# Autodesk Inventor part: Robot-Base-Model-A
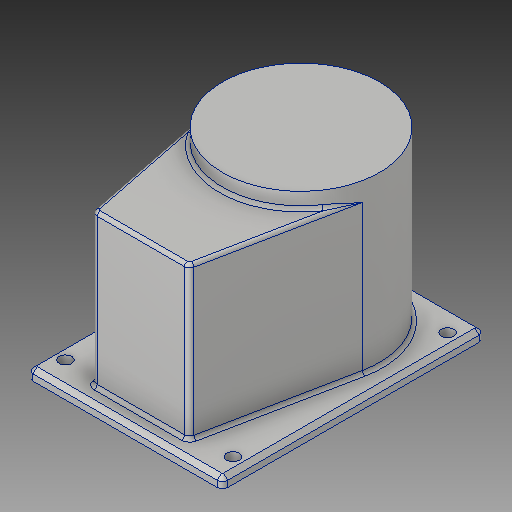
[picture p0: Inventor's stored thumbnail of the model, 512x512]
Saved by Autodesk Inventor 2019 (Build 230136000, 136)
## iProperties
Created: 2018-07
Part Number: Robot-Base-Model-A
Material: Aluminum 6061
Description: 123456
Document SubType Name: Modeling
Designer: Power User
Mass: 12717.4 g
Surface Area: 1979.97 cm^2
Volume: 4710.14 cm^3
Density: 2.7 g/cm^3
Appearance: Aluminum - Flat
Title: GEAR
Author: Power User
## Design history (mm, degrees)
sketch "Sketch6"
  geometry: L1 (93, 125)-(-93, 125); L2 (-93, 125)-(-93, -125); L3 (-93, -125)-(93, -125); L4 (93, -125)-(93, 125); L5 (93, 125)-(-93, -125); L6 (-93, 125)-(93, -125); 1 further point
  constraints: 12 end point, 2 midpoint, 2 parallel, 1 horizontal, 1 perpendicular
  dimensions: "d44" = 250 distance of L3.end L1.start; "d45" = 186 distance of L2.end L3.end
extrude "Extrusion5" new body sketch "Sketch6" distance "d46" = 10; taper "d47" = 0 deg
fillet "Fillet6" dims "d78" = 5
chamfer "Chamfer3" distance "d79" = 4; stored, may be unused: second distance "d80" = 2, angle "d81" = 135 deg
sketch "Sketch7"
  geometry: L1 (-93, -125)-(93, -125) reference; L2 (-73.533, 28.237)-(-45.78, -110); L3 (-45.78, -110)-(45.78, -110); L4 (45.78, -110)-(73.533, 28.237); A1 r 75 centre (0, 43) between (-73.533, 28.237) and (73.533, 28.237); 2 further points
  constraints: 6 end point, 2 point on circle, 2 tangent, 2 vertical alignment, 1 centre point, 1 horizontal, 1 midpoint
  dimensions: "d48" = 150 diameter of A1; "d49" = 168 distance from line of A1.centre L1; "d50" = 91.56 distance of L2.end L3.end; "d51" = 15 distance between parallel lines of L3 L1
extrude "Extrusion6" join sketch "Sketch7" distance "d52" = 160; taper "d53" = 0 deg
extrude "Extrusion7" join sketch "Sketch7" distance "d54" = 145; taper "d55" = 0 deg
sketch "Sketch8"
  geometry: L1 (-93, 125)-(-93, -125) reference; L2 (93, 125)-(-93, 125) reference; 2 further points
  dimensions: "d56" = 13 distance from line of L1 point (-80, 103); "d57" = 22 distance from line of L2 point (-80, 103)
hole "Hole2" sketch "Sketch8" at (-80, 103) diameter "d58" = 12; stored, may be unused: countersink angle "d62" = 90 deg, drill point angle "d64" = 118 deg; dims "d59" = 6, "d60" = 25, "d61" = 10, "d63" = 8
pattern_linear "Rectangular Pattern1" dims "d67" = 205, "d70" = 160
fillet "Fillet2" dims "d74" = 5
fillet "Fillet3" dims "d75" = 3
body "Solid2"
